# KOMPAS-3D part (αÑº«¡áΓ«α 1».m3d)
File: created 29.01.2016 13:47:21, last saved 26.07.2016 19:34:21.
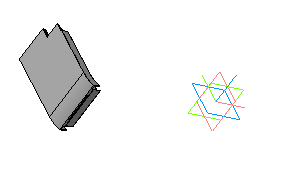
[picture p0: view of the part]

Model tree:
1. Эскиз:1
2. Операция выдавливания:1
     Толщина стенки 1 = 2; Толщина стенки 2 = 8; Расстояние 1 = 1
3. Эскиз:2
4. Операция выдавливания:2
     Толщина стенки 1 = 2; Толщина стенки 2 = 8; Расстояние 1 = 5
5. Эскиз:3
6. Операция выдавливания:3
     Толщина стенки 1 = 2; Толщина стенки 2 = 8; Расстояние 1 = 1
7. Эскиз:4
8. Операция выдавливания:4
     Толщина стенки 1 = 2; Толщина стенки 2 = 2.5; Расстояние 1 = 50
9. Эскиз:5
10. Вырезать элемент выдавливания:1
     Толщина стенки 2 = 1.2; Расстояние 1 = 40
11. Эскиз:6
12. Операция выдавливания:5
     Толщина стенки 1 = 2; Толщина стенки 2 = 2.5; Расстояние 1 = 10
13. Эскиз:7
14. Операция выдавливания:6
     Толщина стенки 1 = 2; Толщина стенки 2 = 8; Расстояние 1 = 1
15. Эскиз:8
16. Операция выдавливания:7
     Толщина стенки 1 = 2; Толщина стенки 2 = 8; Расстояние 1 = 5
17. Эскиз:9
18. Операция выдавливания:8
     Толщина стенки 1 = 2; Толщина стенки 2 = 8; Расстояние 1 = 1
19. Эскиз:10
20. Вырезать элемент выдавливания:2
     Толщина стенки 2 = 1.2; Расстояние 1 = 23
21. Эскиз:11
22. Вырезать элемент выдавливания:3
     Толщина стенки 2 = 1.2; Расстояние 1 = 1
23. Эскиз:12
24. Вырезать элемент выдавливания:4
     Расстояние 1 = 100
25. Эскиз:13
26. Операция выдавливания:9
     Расстояние 1 = 10; Расстояние 2 = 0.4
